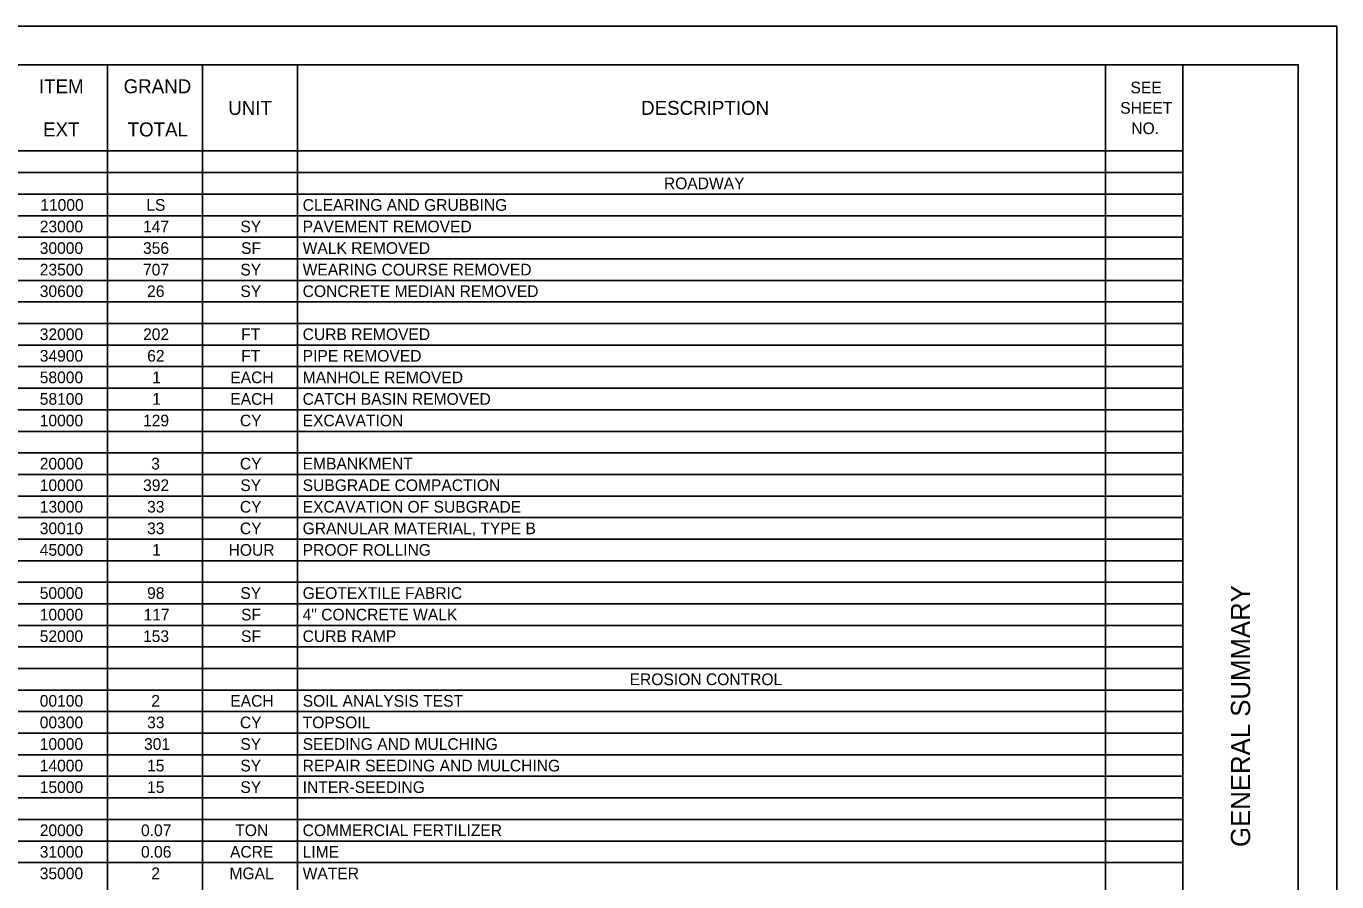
# Model space of a CAD drawing. Extents: x 0 to 34, y 0 to 22.
# Drawn here: x 16.98 to 34, y 10.89 to 22 of the extents above; entities that cross this region are included whole.
import ezdxf

# ---------------------------------------------------------------- set-up
doc = ezdxf.new("R2010")
doc.units = 0
for name, color, linetype in [('SH_Border', 7, 'Continuous'), ('SH_Cut_Line', 7, 'Continuous'), ('SH_Data', 7, 'Continuous'), ('SH_Text', 7, 'Continuous')]:
    doc.layers.add(name, color=color, linetype=linetype)

msp = doc.modelspace()

# ---------------------------------------------------------------- linework, layer by layer
at = {"layer": 'SH_Border'}
msp.add_line((32, 0.5), (32, 21.5), dxfattribs=at)
msp.add_lwpolyline([(1.5, 21.5), (33.5, 21.5), (33.5, 0.5), (1.5, 0.5)], close=True, dxfattribs=at)
at = {"layer": 'SH_Cut_Line'}
msp.add_lwpolyline([(0, 0), (34, 0), (34, 22), (0, 22)], close=True, dxfattribs=at)
at = {"layer": 'SH_Text'}
for p, q in [((1.5, 21.5), (32.001, 21.5)), ((18.035, 21.5), (18.035, 0.502)), ((19.27, 21.5), (19.27, 0.502)), ((20.506, 21.5), (20.506, 0.502)), ((30.997, 21.5), (30.997, 0.502)), ((32.001, 21.5), (32.001, 0.502)), ((1.5, 20.38), (32.001, 20.38)), ((1.5, 20.1), (32.001, 20.1)), ((1.5, 19.82), (32.001, 19.82)), ((1.5, 19.54), (32.001, 19.54)), ((1.5, 19.26), (32.001, 19.26)), ((1.5, 18.98), (32.001, 18.98)), ((1.5, 18.7), (32.001, 18.7)), ((1.5, 18.42), (32.001, 18.42)), ((1.5, 18.14), (32.001, 18.14)), ((1.5, 17.86), (32.001, 17.86)), ((1.5, 17.58), (32.001, 17.58)), ((1.5, 17.3), (32.001, 17.3)), ((1.5, 17.02), (32.001, 17.02)), ((1.5, 16.74), (32.001, 16.74)), ((1.5, 16.46), (32.001, 16.46)), ((1.5, 16.18), (32.001, 16.18)), ((1.5, 15.9), (32.001, 15.9)), ((1.5, 15.62), (32.001, 15.62)), ((1.5, 15.34), (32.001, 15.34)), ((1.5, 15.061), (32.001, 15.061)), ((1.5, 14.781), (32.001, 14.781)), ((1.5, 14.501), (32.001, 14.501)), ((1.5, 14.221), (32.001, 14.221)), ((1.5, 13.941), (32.001, 13.941)), ((1.5, 13.661), (32.001, 13.661)), ((1.5, 13.381), (32.001, 13.381)), ((1.5, 13.101), (32.001, 13.101)), ((1.5, 12.821), (32.001, 12.821)), ((1.5, 12.541), (32.001, 12.541)), ((1.5, 12.261), (32.001, 12.261)), ((1.5, 11.981), (32.001, 11.981)), ((1.5, 11.701), (32.001, 11.701)), ((1.5, 11.421), (32.001, 11.421)), ((1.5, 11.141), (32.001, 11.141))]:
    msp.add_line(p, q, dxfattribs=at)

# ---------------------------------------------------------------- texts
at = {"layer": 'SH_Data'}
msp.add_text('GENERAL SUMMARY', height=0.25, rotation=90, dxfattribs=at).set_placement((32.875, 11.344))
at = {"layer": 'SH_Text'}
for s, height, p in [('ITEM', 0.1818, (17.146, 21.129)), ('GRAND', 0.1818, (18.246, 21.129)), ('SEE ', 0.1515, (31.321, 21.129)), ('UNIT', 0.1818, (19.605, 20.849)), ('DESCRIPTION', 0.18182, (24.966, 20.849)), ('SHEET ', 0.1515, (31.188, 20.864)), ('EXT', 0.1818, (17.2, 20.569)), ('TOTAL', 0.1818, (18.298, 20.569)), ('NO.', 0.1515, (31.332, 20.599)), ('ROADWAY', 0.1515, (25.262, 19.884)), ('11000', 0.1515, (17.164, 19.604)), ('LS', 0.1515, (18.541, 19.604)), ('CLEARING AND GRUBBING', 0.15152, (20.571, 19.604)), ('23000', 0.1515, (17.157, 19.324)), ('147', 0.1515, (18.498, 19.324)), ('SY', 0.1515, (19.762, 19.324)), ('PAVEMENT REMOVED', 0.15152, (20.571, 19.324)), ('30000', 0.1515, (17.157, 19.044)), ('356', 0.1515, (18.498, 19.044)), ('SF', 0.1515, (19.771, 19.044)), ('WALK REMOVED', 0.15152, (20.571, 19.044)), ('23500', 0.1515, (17.157, 18.764)), ('707', 0.1515, (18.498, 18.764)), ('SY', 0.1515, (19.762, 18.764)), ('WEARING COURSE REMOVED', 0.15152, (20.571, 18.764)), ('30600', 0.1515, (17.157, 18.484)), ('26', 0.1515, (18.551, 18.484)), ('SY', 0.1515, (19.762, 18.484)), ('CONCRETE MEDIAN REMOVED', 0.15152, (20.571, 18.484)), ('32000', 0.1515, (17.157, 17.925)), ('202', 0.1515, (18.499, 17.925)), ('FT', 0.1515, (19.773, 17.925)), ('CURB REMOVED', 0.15152, (20.571, 17.925)), ('34900', 0.1515, (17.157, 17.645)), ('62', 0.1515, (18.552, 17.645)), ('FT', 0.1515, (19.773, 17.645)), ('PIPE REMOVED', 0.15152, (20.571, 17.645)), ('58000', 0.1515, (17.157, 17.365)), ('1', 0.152, (18.617, 17.365)), ('EACH', 0.1515, (19.631, 17.365)), ('MANHOLE REMOVED', 0.15152, (20.571, 17.365)), ('58100', 0.1515, (17.157, 17.085)), ('1', 0.152, (18.617, 17.085)), ('EACH', 0.1515, (19.631, 17.085)), ('CATCH BASIN REMOVED', 0.15152, (20.571, 17.085)), ('10000', 0.1515, (17.157, 16.805)), ('129', 0.1515, (18.498, 16.805)), ('CY', 0.1515, (19.756, 16.805)), ('EXCAVATION', 0.1515, (20.571, 16.805)), ('20000', 0.1515, (17.157, 16.245)), ('3', 0.152, (18.604, 16.245)), ('CY', 0.1515, (19.756, 16.245)), ('EMBANKMENT', 0.1515, (20.571, 16.245)), ('10000', 0.1515, (17.157, 15.965)), ('392', 0.1515, (18.499, 15.965)), ('SY', 0.1515, (19.762, 15.965)), ('SUBGRADE COMPACTION', 0.15152, (20.571, 15.965)), ('13000', 0.1515, (17.157, 15.685)), ('33', 0.1515, (18.551, 15.685)), ('CY', 0.1515, (19.756, 15.685)), ('EXCAVATION OF SUBGRADE', 0.15152, (20.571, 15.685)), ('30010', 0.1515, (17.157, 15.405)), ('33', 0.1515, (18.551, 15.405)), ('CY', 0.1515, (19.756, 15.405)), ('GRANULAR MATERIAL, TYPE B', 0.15152, (20.571, 15.405)), ('45000', 0.1515, (17.157, 15.125)), ('1', 0.152, (18.617, 15.125)), ('HOUR', 0.1515, (19.609, 15.125)), ('PROOF ROLLING', 0.15152, (20.571, 15.125)), ('50000', 0.1515, (17.157, 14.565)), ('98', 0.1515, (18.551, 14.565)), ('SY', 0.1515, (19.762, 14.565)), ('GEOTEXTILE FABRIC', 0.15152, (20.571, 14.565)), ('10000', 0.1515, (17.157, 14.285)), ('117', 0.1515, (18.505, 14.285)), ('SF', 0.1515, (19.771, 14.285)), ('4" CONCRETE WALK', 0.15152, (20.571, 14.285)), ('52000', 0.1515, (17.157, 14.005)), ('153', 0.1515, (18.498, 14.005)), ('SF', 0.1515, (19.771, 14.005)), ('CURB RAMP', 0.1515, (20.571, 14.005)), ('EROSION CONTROL', 0.15152, (24.817, 13.445)), ('00100', 0.1515, (17.157, 13.165)), ('2', 0.152, (18.605, 13.165)), ('EACH', 0.1515, (19.631, 13.165)), ('SOIL ANALYSIS TEST', 0.15152, (20.571, 13.165)), ('00300', 0.1515, (17.157, 12.885)), ('33', 0.1515, (18.551, 12.885)), ('CY', 0.1515, (19.756, 12.885)), ('TOPSOIL', 0.1515, (20.571, 12.885)), ('10000', 0.1515, (17.157, 12.605)), ('301', 0.1515, (18.511, 12.605)), ('SY', 0.1515, (19.762, 12.605)), ('SEEDING AND MULCHING', 0.15152, (20.571, 12.605)), ('14000', 0.1515, (17.157, 12.325)), ('15', 0.1515, (18.551, 12.325)), ('SY', 0.1515, (19.762, 12.325)), ('REPAIR SEEDING AND MULCHING', 0.15152, (20.571, 12.325)), ('15000', 0.1515, (17.157, 12.045)), ('15', 0.1515, (18.551, 12.045)), ('SY', 0.1515, (19.762, 12.045)), ('INTER-SEEDING', 0.15152, (20.571, 12.045)), ('20000', 0.1515, (17.157, 11.485)), ('0.07', 0.1515, (18.472, 11.485)), ('TON', 0.1515, (19.696, 11.485)), ('COMMERCIAL FERTILIZER', 0.15152, (20.571, 11.485)), ('31000', 0.1515, (17.157, 11.205)), ('0.06', 0.1515, (18.472, 11.205)), ('ACRE', 0.1515, (19.628, 11.205)), ('LIME', 0.1515, (20.571, 11.205)), ('35000', 0.1515, (17.157, 10.925)), ('2', 0.152, (18.605, 10.925)), ('MGAL', 0.1515, (19.621, 10.925)), ('WATER', 0.1515, (20.571, 10.925))]:
    msp.add_text(s, height=height, dxfattribs=at).set_placement(p)

doc.saveas('drawing.dxf')
